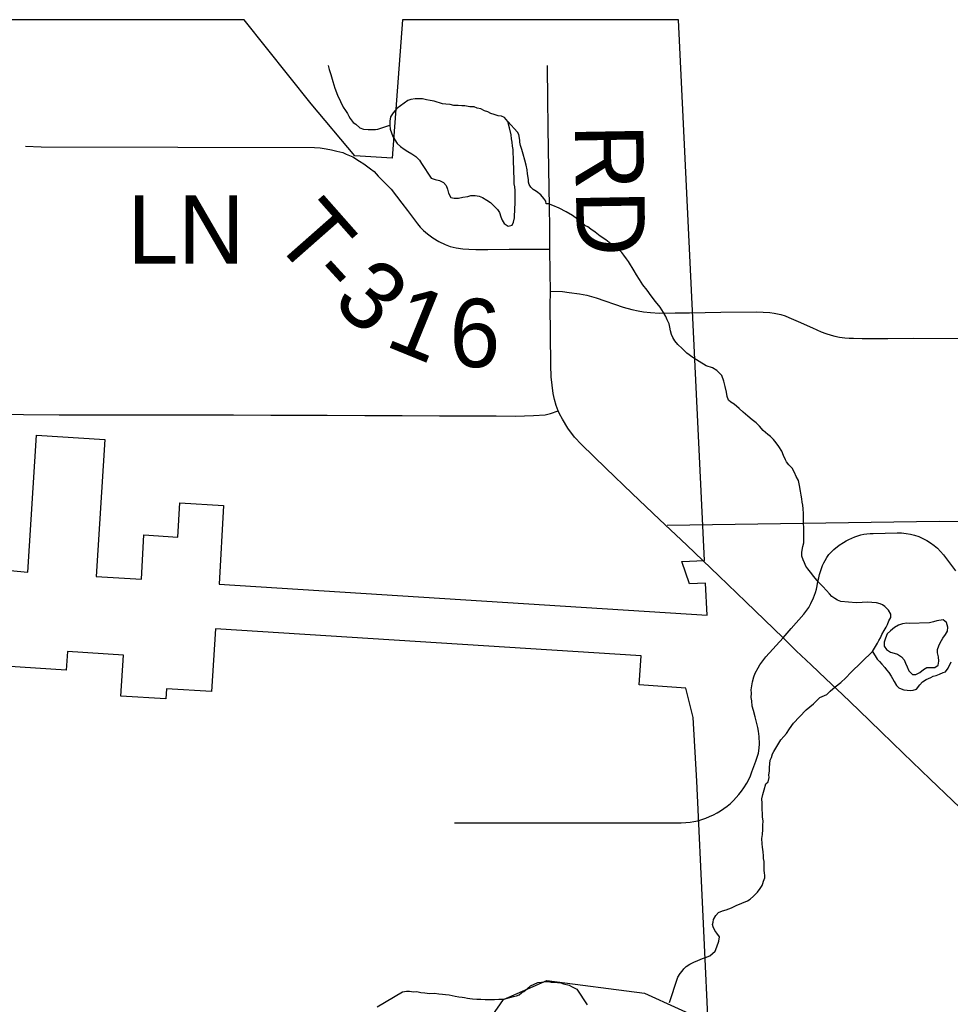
# Model space of a CAD drawing. Extents: x -11.4 to 84.1, y 11.1 to 59.
# Drawn here: x 29.384 to 30.157, y 46.631 to 47.448 of the extents above; entities that cross this region are included whole.
import ezdxf

# ---------------------------------------------------------------- set-up
doc = ezdxf.new("R2010")
doc.units = 0
for name, color, linetype in [('GM_X_Corporation', 7, 'Continuous'), ('GM_X_County_Road', 7, 'Continuous'), ('GM_X_County_Road_Text', 7, 'Continuous'), ('GM_X_Major_River', 7, 'Continuous'), ('GM_X_Minor_Lake', 7, 'Continuous'), ('GM_X_Minor_River', 7, 'Continuous'), ('GM_X_Rail_Line', 7, 'Continuous'), ('GM_X_Township_Road', 7, 'Continuous'), ('GM_X_Township_Road_Text', 7, 'Continuous')]:
    doc.layers.add(name, color=color, linetype=linetype)

msp = doc.modelspace()

# ---------------------------------------------------------------- linework, layer by layer
at = {"layer": 'GM_X_Corporation'}
for p, q in [((29.57058, 47.44833), (29.17063, 47.44833)), ((29.93116, 47.44833), (29.70188, 47.44833))]:
    msp.add_line(p, q, dxfattribs=at)
for points in [[(29.30011, 46.99808), (29.39089, 46.98957), (29.3981, 47.10317), (29.4548, 47.09957), (29.4476, 46.98597), (29.4852, 46.98359), (29.48717, 47.02046), (29.51547, 47.01866), (29.51698, 47.04705), (29.55337, 47.04474), (29.5499, 46.97949), (29.95489, 46.95381), (29.95361, 46.98041), (29.94037, 46.97977), (29.93379, 46.99842), (29.9527, 46.99932), (29.93116, 47.44833)], [(29.70188, 47.44833), (29.69352, 47.33324), (29.66248, 47.33518), (29.62607, 47.37857), (29.57058, 47.44833)], [(29.28069, 46.4633), (29.48694, 46.4478), (29.48338, 46.38829), (29.69847, 46.3706), (29.70625, 46.49473), (29.83524, 46.48587), (29.96225, 46.47876), (29.94645, 46.81602), (29.94322, 46.8688), (29.93718, 46.89312), (29.89848, 46.896), (29.90015, 46.91994), (29.54669, 46.94235), (29.54344, 46.89034), (29.50614, 46.89272), (29.5056, 46.8842), (29.4682, 46.88659), (29.47036, 46.92058), (29.42378, 46.92356), (29.4228, 46.90804), (29.29517, 46.9163)]]:
    msp.add_lwpolyline(points, dxfattribs=at)
at = {"layer": 'GM_X_County_Road'}
for points in [[(29.82439, 47.25768), (29.82418, 47.27549), (29.82398, 47.2933), (29.82344, 47.32436), (29.82315, 47.34126), (29.82285, 47.35815), (29.82267, 47.38318), (29.82249, 47.40821), (29.82247, 47.41026)], [(29.8248, 47.22289), (29.82448, 47.23842), (29.82439, 47.25768)], [(29.83115, 47.1235), (29.82948, 47.12794), (29.82806, 47.13299), (29.82706, 47.13783), (29.82612, 47.14466), (29.82548, 47.15176), (29.82506, 47.16133), (29.82475, 47.18705), (29.82464, 47.21055), (29.8248, 47.22289)], [(30.01811, 46.93493), (30.00254, 46.94995), (29.98696, 46.96498), (29.9645, 46.98644), (29.9512, 46.99915), (29.93791, 47.01184), (29.91543, 47.03329), (29.90411, 47.0441), (29.89279, 47.0549), (29.87093, 47.07595), (29.85051, 47.0955), (29.84468, 47.10165), (29.83936, 47.10896), (29.83469, 47.11658), (29.83227, 47.1209), (29.83115, 47.1235)], [(30.3395, 46.62624), (30.31717, 46.64784), (30.29939, 46.66505), (30.28161, 46.68225), (30.26745, 46.69595), (30.2533, 46.70964), (30.23081, 46.73107), (30.20832, 46.75251), (30.19277, 46.76733), (30.17722, 46.78215), (30.15863, 46.79979), (30.14004, 46.81744), (30.11773, 46.83906), (30.0993, 46.85693), (30.08087, 46.87479), (30.06721, 46.88781), (30.05354, 46.90083), (30.04123, 46.91256), (30.02893, 46.92428), (30.01811, 46.93493)]]:
    msp.add_lwpolyline(points, dxfattribs=at)
at = {"layer": 'GM_X_Major_River'}
msp.add_lwpolyline([(29.68106, 46.62853), (29.702, 46.641), (29.70541, 46.64141), (29.70769, 46.64143), (29.71112, 46.64109), (29.71378, 46.64111), (29.71721, 46.64039), (29.72063, 46.64004), (29.72443, 46.6397), (29.72862, 46.63974), (29.73204, 46.6394), (29.73509, 46.63905), (29.73775, 46.63869), (29.7408, 46.63834), (29.74308, 46.63799), (29.74575, 46.63725), (29.74879, 46.6369), (29.75146, 46.63655), (29.75336, 46.63619), (29.75603, 46.63583), (29.75793, 46.63547), (29.76022, 46.63511), (29.76365, 46.63477), (29.76707, 46.6348), (29.77049, 46.63446), (29.77467, 46.6345), (29.77847, 46.63454), (29.78189, 46.63495), (29.78531, 46.63499), (29.78796, 46.63539), (29.791, 46.63618), (29.79403, 46.63697), (29.79668, 46.63776), (29.79895, 46.63854), (29.80083, 46.64008), (29.80272, 46.64124), (29.80535, 46.64355), (29.80837, 46.64586), (29.81139, 46.64741), (29.81442, 46.64858), (29.81745, 46.64899), (29.82049, 46.6494), (29.82315, 46.64943), (29.82543, 46.64907), (29.82809, 46.6491), (29.83076, 46.64874), (29.83342, 46.64839), (29.83571, 46.64765), (29.84029, 46.64656), (29.8422, 46.64544), (29.84449, 46.64432), (29.84679, 46.6432), (29.85531, 46.63012)], dxfattribs=at)
at = {"layer": 'GM_X_Minor_Lake'}
for points in [[(29.77008, 47.37268), (29.76704, 47.37418), (29.764, 47.37492), (29.76134, 47.37604), (29.75793, 47.37602), (29.75376, 47.37675), (29.75111, 47.37673), (29.74808, 47.37709), (29.74467, 47.37706), (29.74163, 47.3778), (29.73784, 47.37816), (29.73518, 47.37852), (29.72835, 47.38075), (29.72494, 47.3811), (29.7219, 47.38184), (29.71849, 47.38258), (29.71243, 47.38253), (29.70902, 47.38213), (29.70638, 47.38135), (29.70336, 47.37906), (29.70035, 47.37676), (29.69733, 47.37446), (29.69433, 47.37102), (29.69207, 47.36759), (29.69134, 47.36417), (29.69136, 47.36076), (29.69177, 47.35735), (29.69408, 47.35129), (29.69561, 47.34864), (29.69753, 47.34562), (29.7002, 47.34298), (29.70324, 47.34073), (29.70629, 47.33885), (29.70971, 47.33698), (29.71313, 47.33472), (29.71618, 47.33171), (29.71782, 47.3288)], [(29.79073, 47.35838), (29.78946, 47.36371), (29.78678, 47.36711), (29.78412, 47.36823), (29.78147, 47.36859), (29.77805, 47.3697), (29.77539, 47.37044), (29.77273, 47.37194), (29.77008, 47.37268)], [(29.71782, 47.3288), (29.72576, 47.31659), (29.72918, 47.31548), (29.73259, 47.31474), (29.73601, 47.31325), (29.7383, 47.31061), (29.73946, 47.30758), (29.74024, 47.30417), (29.74215, 47.30077), (29.74481, 47.30003), (29.7486, 47.30005), (29.752, 47.30084), (29.75617, 47.30162), (29.75881, 47.3024), (29.76222, 47.30242), (29.76564, 47.30169), (29.7683, 47.30057), (29.7721, 47.29832), (29.77514, 47.29644), (29.78086, 47.29079), (29.7824, 47.28814), (29.78356, 47.28473), (29.78471, 47.28171), (29.78625, 47.27906), (29.78967, 47.27681), (29.79308, 47.27759), (29.79419, 47.28025), (29.79493, 47.28367), (29.79491, 47.28633), (29.79527, 47.28937), (29.79525, 47.29202), (29.79561, 47.29506), (29.79553, 47.30645), (29.79513, 47.30948), (29.79473, 47.31213), (29.79469, 47.31783), (29.79429, 47.32086), (29.79421, 47.33376), (29.7938, 47.33717), (29.79378, 47.34059), (29.79339, 47.34324), (29.79298, 47.34666), (29.79259, 47.34931), (29.79218, 47.35272), (29.79073, 47.35838)], [(30.12258, 46.9468), (30.12063, 46.947), (30.11723, 46.9466), (30.11383, 46.94544), (30.11043, 46.94352), (30.10704, 46.94084), (30.1044, 46.93816), (30.10291, 46.93474), (30.1018, 46.93131), (30.10182, 46.9279), (30.10373, 46.92525), (30.10716, 46.923), (30.11019, 46.92226), (30.11285, 46.92152), (30.11628, 46.91927), (30.11857, 46.91663), (30.11972, 46.91398), (30.12088, 46.91095), (30.12242, 46.90755), (30.12547, 46.90453)], [(30.12547, 46.90453), (30.12812, 46.90455), (30.13152, 46.90609), (30.13453, 46.90877), (30.13717, 46.9103), (30.14399, 46.91035), (30.14663, 46.91226), (30.14736, 46.91568), (30.14696, 46.9191), (30.14618, 46.92251), (30.14616, 46.92517), (30.14728, 46.92821), (30.1484, 46.93087), (30.15064, 46.93468), (30.1529, 46.93773), (30.15439, 46.9404), (30.15475, 46.94382), (30.15359, 46.9476), (30.15092, 46.94986), (30.14562, 46.94907), (30.14297, 46.94829), (30.13957, 46.94751), (30.12258, 46.9468)]]:
    msp.add_lwpolyline(points, dxfattribs=at)
at = {"layer": 'GM_X_Minor_River'}
for points in [[(29.64024, 47.41026), (29.64103, 47.40687), (29.6426, 47.4027), (29.64418, 47.39702), (29.64577, 47.39133), (29.64812, 47.38565), (29.65046, 47.38035), (29.65279, 47.37581), (29.65473, 47.37279), (29.65628, 47.37052), (29.65744, 47.36826), (29.65861, 47.36637), (29.66093, 47.36297), (29.66322, 47.36147), (29.66668, 47.35846), (29.66973, 47.35735), (29.67354, 47.35701), (29.67696, 47.35704), (29.67962, 47.35707), (29.68151, 47.35747), (29.69136, 47.36076)], [(29.90852, 47.21906), (29.90505, 47.22359), (29.90158, 47.22812), (29.89886, 47.23265), (29.89616, 47.23643), (29.89422, 47.23983), (29.88957, 47.24739), (29.88802, 47.24966), (29.88571, 47.25267), (29.88416, 47.25494), (29.88185, 47.2572), (29.87879, 47.25945), (29.87495, 47.26207), (29.87073, 47.26545), (29.86614, 47.26845), (29.86192, 47.27182), (29.85847, 47.27445), (29.85579, 47.27633), (29.85387, 47.27707), (29.85157, 47.27933), (29.84735, 47.28271), (29.84313, 47.28571), (29.83778, 47.28869), (29.83204, 47.29168), (29.82669, 47.29391), (29.82325, 47.29539), (29.82135, 47.29537), (29.82095, 47.29765), (29.8194, 47.29992), (29.81671, 47.30293), (29.81325, 47.30556), (29.81057, 47.30743), (29.80865, 47.30931), (29.8071, 47.31158), (29.8067, 47.31348), (29.80668, 47.31538), (29.80628, 47.31727), (29.80586, 47.32031), (29.80544, 47.32373), (29.80464, 47.32752), (29.80345, 47.33169), (29.80225, 47.33663), (29.80107, 47.34042), (29.79989, 47.34382), (29.79947, 47.34648), (29.79945, 47.34838), (29.79864, 47.35294), (29.79748, 47.35483), (29.78946, 47.36371)], [(30.09733, 46.93275), (30.09883, 46.93505), (30.09994, 46.93772), (30.1018, 46.94116), (30.10367, 46.94384), (30.10478, 46.94613), (30.10589, 46.94919), (30.10737, 46.95186), (30.10734, 46.95452), (30.1054, 46.95793), (30.10233, 46.96094), (30.10041, 46.96244), (30.0985, 46.96318), (30.09545, 46.96391), (30.09165, 46.96425), (30.08784, 46.96459), (30.08367, 46.96417), (30.07872, 46.96413), (30.06579, 46.96513), (30.06312, 46.96625), (30.06082, 46.96775), (30.05852, 46.96925), (30.05659, 46.97151), (30.0539, 46.97414), (30.05082, 46.97753), (30.04736, 46.9813), (30.0435, 46.98582), (30.0408, 46.9896), (30.03849, 46.99224), (30.03694, 46.9945), (30.03577, 46.99715), (30.0346, 46.9998), (30.03342, 47.00283), (30.03339, 47.00588), (30.03375, 47.00778), (30.03447, 47.01083), (30.0352, 47.01388), (30.03516, 47.01692), (30.03513, 47.01996), (30.03509, 47.023), (30.03505, 47.02642), (30.03501, 47.03022), (30.03495, 47.03478), (30.03492, 47.03821), (30.03449, 47.04201), (30.03445, 47.04505), (30.03366, 47.0477), (30.03363, 47.05036), (30.03284, 47.05339), (30.03242, 47.05681), (30.03161, 47.06137), (30.03079, 47.06554), (30.02886, 47.06894), (30.0273, 47.07235), (30.02536, 47.07575), (30.02266, 47.07877), (30.02073, 47.08103), (30.01995, 47.08292), (30.01839, 47.08633), (30.01683, 47.09011), (30.0145, 47.09389), (30.01219, 47.09691), (30.00988, 47.09955), (30.00757, 47.10219), (30.00527, 47.10369), (30.00143, 47.10707), (29.99834, 47.11084), (29.99565, 47.11348), (29.9922, 47.1161), (29.98874, 47.11911), (29.9849, 47.12249), (29.98145, 47.1255), (29.97723, 47.12888), (29.97454, 47.13075), (29.97263, 47.13226), (29.97145, 47.13529), (29.97103, 47.13908), (29.96983, 47.14363), (29.96864, 47.14819), (29.96707, 47.15273), (29.96476, 47.15499), (29.96284, 47.15687), (29.95939, 47.15912), (29.95405, 47.16097), (29.94831, 47.16433), (29.94295, 47.1677), (29.93796, 47.17145), (29.93412, 47.17522), (29.93066, 47.1786), (29.92796, 47.18162), (29.92641, 47.18426), (29.92524, 47.18691), (29.92444, 47.18995), (29.92403, 47.19298), (29.92324, 47.19564), (29.92168, 47.19904), (29.92051, 47.20169), (29.91857, 47.2051), (29.91585, 47.20963), (29.912, 47.21415), (29.90852, 47.21906)], [(30.09212, 46.92358), (30.09622, 46.93046), (30.09733, 46.93275)], [(29.93026, 46.65232), (29.93067, 46.65317), (29.93254, 46.65622), (29.93404, 46.65814), (29.93554, 46.66006), (29.93741, 46.66198), (29.94043, 46.66391), (29.94383, 46.66546), (29.94724, 46.66702), (29.95102, 46.66857), (29.95367, 46.66936), (29.95707, 46.67092), (29.95933, 46.67284), (29.96159, 46.67476), (29.96307, 46.6782), (29.96454, 46.68316), (29.96525, 46.68659), (29.96294, 46.68961), (29.96139, 46.69187), (29.95984, 46.6949), (29.95943, 46.69679), (29.95979, 46.6987), (29.96015, 46.70098), (29.96201, 46.70442), (29.96426, 46.70673), (29.96766, 46.70828), (29.9707, 46.70907), (29.97297, 46.70986), (29.97524, 46.71064), (29.97902, 46.71258), (29.98847, 46.71647), (29.99074, 46.71802), (29.99337, 46.72032), (29.99675, 46.72378), (29.999, 46.72684), (30.00049, 46.72914), (30.00123, 46.73105), (30.00159, 46.73295), (30.0027, 46.73563), (30.00267, 46.73753), (30.00265, 46.73981), (30.00225, 46.7417), (30.00222, 46.74399), (30.00218, 46.74741), (30.00216, 46.74931), (30.00175, 46.75158), (30.00172, 46.75387), (30.0013, 46.75728), (30.00088, 46.76108), (30.00047, 46.76374), (30.00042, 46.7683), (30.00075, 46.77173), (30.00109, 46.77591), (30.00105, 46.77933), (30.00139, 46.78276), (30.00097, 46.78617), (30.00093, 46.7896), (30.00052, 46.79188), (30.0005, 46.79415), (30.00046, 46.79758), (30.00041, 46.80138), (30.00113, 46.80481), (30.00223, 46.80862), (30.00369, 46.81358), (30.00557, 46.8155), (30.00629, 46.81893), (30.00626, 46.82121), (30.00661, 46.82425), (30.00657, 46.82729), (30.00692, 46.83034), (30.00726, 46.83338), (30.00838, 46.83567), (30.0091, 46.83872), (30.01022, 46.84064), (30.01619, 46.8502), (30.01844, 46.85288), (30.02069, 46.85557), (30.02331, 46.8594), (30.02667, 46.86399), (30.03155, 46.86936), (30.03719, 46.87512), (30.04321, 46.88013), (30.04847, 46.8855), (30.05414, 46.88784), (30.05715, 46.89053), (30.06129, 46.89437), (30.06581, 46.89784), (30.06995, 46.90168), (30.07408, 46.90629), (30.09212, 46.92358)], [(30.09212, 46.92358), (30.096, 46.91715), (30.09792, 46.91527), (30.09984, 46.91301), (30.10254, 46.91037), (30.1037, 46.90849), (30.10562, 46.90622), (30.10756, 46.9032), (30.10872, 46.90131), (30.11027, 46.89866), (30.11221, 46.89526), (30.11414, 46.89338), (30.11604, 46.89264), (30.11833, 46.8919), (30.121, 46.89155), (30.12366, 46.8912), (30.12594, 46.8916), (30.12859, 46.89238), (30.13159, 46.89584), (30.13384, 46.89852), (30.13686, 46.90045), (30.13875, 46.90123), (30.14064, 46.90201), (30.14253, 46.90317), (30.14518, 46.90358), (30.14783, 46.90474), (30.15086, 46.90629), (30.15275, 46.90669), (30.155, 46.90976), (30.1576, 46.9151)], [(29.92358, 46.63221), (29.93026, 46.65232)]]:
    msp.add_lwpolyline(points, dxfattribs=at)
at = {"layer": 'GM_X_Rail_Line'}
for points in [[(31.09667, 47.00784), (31.01806, 47.03518), (30.91554, 47.04792), (30.84257, 47.05314), (30.74701, 47.0485), (30.64218, 47.04155), (30.47654, 47.03402), (30.34043, 47.0288), (30.14757, 47.0317), (29.9217, 47.02822)], [(29.77633, 46.62095), (29.78588, 46.63449), (29.82173, 46.65031), (29.90294, 46.63976), (29.95883, 46.61445)]]:
    msp.add_lwpolyline(points, dxfattribs=at)
at = {"layer": 'GM_X_Township_Road'}
for points in [[(29.82439, 47.25768), (29.82418, 47.27549), (29.82398, 47.2933), (29.82344, 47.32436), (29.82315, 47.34126), (29.82285, 47.35815), (29.82267, 47.38318), (29.82249, 47.40821), (29.82247, 47.41026)], [(29.3889, 47.34319), (29.4021, 47.34264), (29.62887, 47.34223), (29.63358, 47.34183), (29.63856, 47.3412), (29.64305, 47.34022), (29.6474, 47.33905), (29.65233, 47.33797), (29.65525, 47.33672), (29.66068, 47.33456), (29.66633, 47.33088), (29.67001, 47.32873), (29.6753, 47.32433), (29.6784, 47.32216), (29.6818, 47.31846), (29.68539, 47.31487), (29.69257, 47.30756), (29.70145, 47.29598), (29.70603, 47.28975), (29.71438, 47.27889), (29.71671, 47.27615), (29.71945, 47.27337), (29.72281, 47.27045), (29.72729, 47.26705), (29.73214, 47.26422), (29.7373, 47.26157), (29.7416, 47.2601), (29.74641, 47.25893), (29.7521, 47.25812), (29.75708, 47.25763), (29.76287, 47.25749), (29.77287, 47.2574), (29.79055, 47.25763), (29.82439, 47.25768)], [(29.8248, 47.22289), (29.82448, 47.23842), (29.82439, 47.25768)], [(29.83115, 47.1235), (29.82948, 47.12794), (29.82806, 47.13299), (29.82706, 47.13783), (29.82612, 47.14466), (29.82548, 47.15176), (29.82506, 47.16133), (29.82475, 47.18705), (29.82464, 47.21055), (29.8248, 47.22289)], [(29.8248, 47.22289), (29.83495, 47.22257), (29.84022, 47.22188), (29.84886, 47.22058), (29.85498, 47.21959), (29.86285, 47.21745), (29.88518, 47.20965), (29.89229, 47.20758), (29.89769, 47.20646), (29.9022, 47.20566), (29.90801, 47.2051), (29.91541, 47.20458), (29.92831, 47.20478)], [(29.92831, 47.20478), (29.94022, 47.20496), (29.96619, 47.20543), (29.99568, 47.20557), (30.00132, 47.20549), (30.00703, 47.20509), (30.01052, 47.20455), (30.01603, 47.20341), (30.01963, 47.20225), (30.02279, 47.20098), (30.0265, 47.1994), (30.0306, 47.19757), (30.04228, 47.19253), (30.04962, 47.1891), (30.05336, 47.18766), (30.05781, 47.18622), (30.06083, 47.1855), (30.06487, 47.18478), (30.0692, 47.18417), (30.07279, 47.18384), (30.07634, 47.18372), (30.08367, 47.18347), (30.10494, 47.18362), (30.12621, 47.18375), (30.19935, 47.18359)], [(29.31887, 47.12078), (29.38733, 47.12046), (29.41706, 47.12026), (29.44679, 47.12006), (29.47312, 47.12016), (29.49944, 47.12026), (29.53051, 47.12018), (29.56158, 47.12009), (29.59265, 47.12), (29.61607, 47.11993), (29.6395, 47.11987), (29.67057, 47.11973), (29.70164, 47.11959), (29.73271, 47.11946), (29.76377, 47.11932), (29.77982, 47.11926), (29.79588, 47.11919), (29.81064, 47.11957), (29.82039, 47.12006), (29.82495, 47.12116), (29.83115, 47.1235)], [(30.01811, 46.93493), (30.00254, 46.94995), (29.98696, 46.96498), (29.9645, 46.98644), (29.9512, 46.99915), (29.93791, 47.01184), (29.91543, 47.03329), (29.90411, 47.0441), (29.89279, 47.0549), (29.87093, 47.07595), (29.85051, 47.0955), (29.84468, 47.10165), (29.83936, 47.10896), (29.83469, 47.11658), (29.83227, 47.1209), (29.83115, 47.1235)], [(30.01811, 46.93493), (30.02474, 46.94275), (30.0351, 46.95451), (30.03929, 46.96009), (30.04109, 46.96347), (30.04315, 46.96818), (30.04494, 46.97266), (30.04565, 46.97538), (30.04623, 46.97814), (30.04682, 46.98177), (30.04761, 46.9849), (30.04827, 46.98744), (30.04904, 46.98993), (30.04987, 46.99247), (30.05079, 46.99497), (30.05174, 46.99736), (30.05277, 46.9993), (30.05417, 47.00154), (30.05594, 47.00412), (30.06001, 47.00834), (30.06446, 47.01191), (30.0681, 47.01416), (30.07032, 47.01552), (30.07265, 47.01676), (30.07501, 47.01785), (30.07743, 47.01883), (30.07994, 47.01967), (30.08245, 47.02037), (30.08501, 47.02092), (30.08757, 47.02133), (30.09017, 47.02161), (30.09278, 47.02173), (30.10264, 47.02194), (30.11268, 47.02216), (30.11638, 47.02209), (30.12002, 47.02174), (30.12363, 47.02112), (30.12718, 47.02022), (30.13064, 47.01904), (30.134, 47.01759), (30.13727, 47.0159), (30.14039, 47.01395), (30.14333, 47.01177), (30.14608, 47.00938), (30.14868, 47.00677), (30.15105, 47.00396), (30.16117, 46.9907)], [(29.7451, 46.78144), (29.93345, 46.78133), (29.93727, 46.78151), (29.94073, 46.78176), (29.9439, 46.78232), (29.94722, 46.7831), (29.95053, 46.78405), (29.95376, 46.78518), (29.95693, 46.78646), (29.96006, 46.78792), (29.96309, 46.78953), (29.96603, 46.7913), (29.96888, 46.79322), (29.97157, 46.79528), (29.97423, 46.79749), (29.97674, 46.79984), (29.97911, 46.8023), (29.98134, 46.80489), (29.98342, 46.80761), (29.98542, 46.81041), (29.98778, 46.81431), (29.9894, 46.81734), (29.99082, 46.82045), (29.9921, 46.82363), (29.99542, 46.83251), (29.99651, 46.83571), (29.99747, 46.8393), (29.998, 46.84323), (29.99849, 46.84681), (29.99819, 46.85305), (29.9975, 46.85737), (29.99701, 46.8604), (29.99609, 46.8638), (29.99473, 46.86924), (29.99336, 46.87467), (29.99238, 46.87813), (29.99189, 46.88251), (29.99151, 46.88529), (29.99164, 46.88888), (29.99157, 46.89184), (29.99189, 46.89505), (29.9925, 46.89845), (29.99368, 46.90253), (29.99479, 46.90549), (29.99714, 46.91013), (29.99878, 46.91244), (30.00361, 46.91914), (30.01811, 46.93493)], [(30.3395, 46.62624), (30.31717, 46.64784), (30.29939, 46.66505), (30.28161, 46.68225), (30.26745, 46.69595), (30.2533, 46.70964), (30.23081, 46.73107), (30.20832, 46.75251), (30.19277, 46.76733), (30.17722, 46.78215), (30.15863, 46.79979), (30.14004, 46.81744), (30.11773, 46.83906), (30.0993, 46.85693), (30.08087, 46.87479), (30.06721, 46.88781), (30.05354, 46.90083), (30.04123, 46.91256), (30.02893, 46.92428), (30.01811, 46.93493)]]:
    msp.add_lwpolyline(points, dxfattribs=at)

# ---------------------------------------------------------------- texts
at = {"layer": 'GM_X_County_Road_Text'}
msp.add_text('RD', height=0.056818, rotation=270.98722, dxfattribs=at).set_placement((29.84504, 47.36127))
at = {"layer": 'GM_X_Township_Road_Text'}
for s, height, rotation, p in [('LN', 0.056818, 0.00001, (29.47353, 47.24572)), ('T', 0.05682, 311.40968, (29.59281, 47.26661)), ('-', 0.05682, 312.47109, (29.62169, 47.23388)), ('3', 0.05682, 318.74017, (29.64228, 47.21193)), ('1', 0.05682, 337.82299, (29.68606, 47.17805)), ('6', 0.05682, 358.6338, (29.74038, 47.16028))]:
    msp.add_text(s, height=height, rotation=rotation, dxfattribs=at).set_placement(p)

doc.saveas('drawing.dxf')
